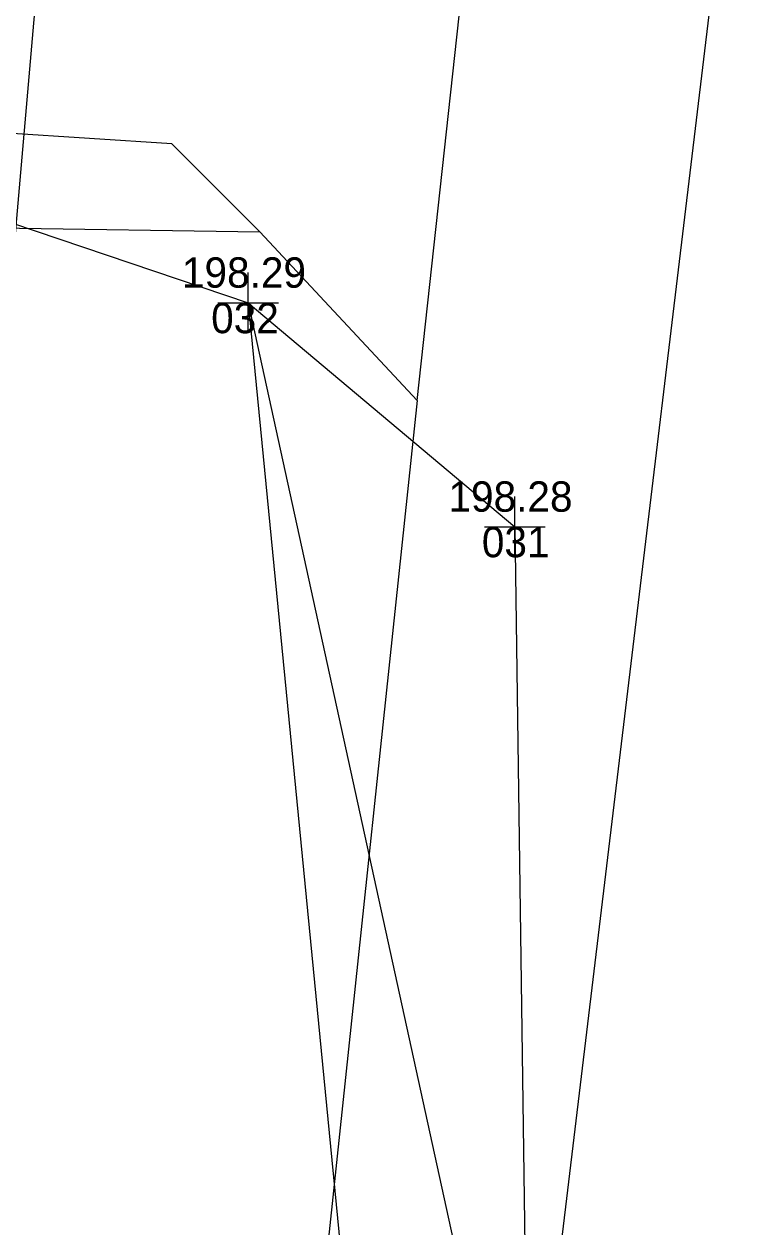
# Model space of a CAD drawing. Extents: x -706655 to -706193, y -1036183 to -1035040.
# Drawn here: x -706624.14 to -706612.36, y -1035127.71 to -1035107.9 of the extents above; entities that cross this region are included whole.
import ezdxf

# ---------------------------------------------------------------- set-up
doc = ezdxf.new("R2010")
doc.units = 0
for name, color, linetype in [('CETIN', 7, 'Continuous'), ('Hranice parcel', 7, 'Continuous'), ('křížky', 7, 'Continuous'), ('Stávající terén', 7, 'Continuous'), ('výšky', 7, 'Continuous'), ('čísla bodu', 7, 'Continuous')]:
    doc.layers.add(name, color=color, linetype=linetype)

msp = doc.modelspace()

# ---------------------------------------------------------------- linework, layer by layer
at = {"layer": 'CETIN'}
msp.add_lwpolyline([(-706632.29, -1035178.176), (-706624.38, -1035112.55), (-706623.72, -1035104.98), (-706623.414, -1035102.598), (-706615.872, -1035043.919)], dxfattribs=at)
at = {"layer": 'Hranice parcel'}
for p, q in [((-706617.66, -1035114.1), (-706615.7, -1035096.22)), ((-706650.337, -1035110.851), (-706620.25, -1035111.32)), ((-706620.25, -1035111.32), (-706617.66, -1035114.1)), ((-706617.66, -1035114.1), (-706620.85, -1035144.24))]:
    msp.add_line(p, q, dxfattribs=at)
msp.add_lwpolyline([(-706620.25, -1035111.32), (-706621.7, -1035109.87), (-706632.56, -1035109.17), (-706644.89, -1035107.95), (-706648.091, -1035107.907)], dxfattribs=at)
at = {"layer": 'křížky'}
for p, q in [((-706620.44, -1035112.99), (-706620.44, -1035111.99)), ((-706620.94, -1035112.49), (-706619.94, -1035112.49)), ((-706620.44, -1035112.49), (-706620.44, -1035112.49)), ((-706616.05, -1035116.68), (-706616.05, -1035115.68)), ((-706616.55, -1035116.18), (-706615.55, -1035116.18)), ((-706616.05, -1035116.18), (-706616.05, -1035116.18))]:
    msp.add_line(p, q, dxfattribs=at)
at = {"layer": 'Stávající terén'}
for points in [[(-706608.917, -1035075.29), (-706610.31, -1035086.81), (-706611.88, -1035099.66), (-706615.39, -1035128.84), (-706617.25, -1035146.23)], [(-706630.18, -1035109.2), (-706620.44, -1035112.49), (-706618.86, -1035128.69), (-706620.88, -1035145.19)], [(-706620.44, -1035112.49), (-706616.88, -1035128.78), (-706618.96, -1035145.46)], [(-706620.44, -1035112.49), (-706616.05, -1035116.18), (-706615.87, -1035128.82), (-706617.82, -1035146.02)]]:
    msp.add_lwpolyline(points, dxfattribs=at)
at = {"layer": 'čísla bodu'}
for p, q in [((-706620.44, -1035112.99), (-706620.44, -1035111.99)), ((-706620.94, -1035112.49), (-706619.94, -1035112.49)), ((-706620.44, -1035112.49), (-706620.44, -1035112.49)), ((-706616.05, -1035116.68), (-706616.05, -1035115.68)), ((-706616.55, -1035116.18), (-706615.55, -1035116.18)), ((-706616.05, -1035116.18), (-706616.05, -1035116.18))]:
    msp.add_line(p, q, dxfattribs=at)

# ---------------------------------------------------------------- texts
at = {"layer": 'výšky'}
for s, p in [('198.29', (-706621.534, -1035112.24)), ('198.28', (-706617.142, -1035115.93))]:
    msp.add_text(s, height=0.5, dxfattribs=at).set_placement(p)
at = {"layer": 'čísla bodu'}
for s, p in [('032', (-706621.052, -1035112.99)), ('031', (-706616.592, -1035116.68))]:
    msp.add_text(s, height=0.5, dxfattribs=at).set_placement(p)

doc.saveas('drawing.dxf')
